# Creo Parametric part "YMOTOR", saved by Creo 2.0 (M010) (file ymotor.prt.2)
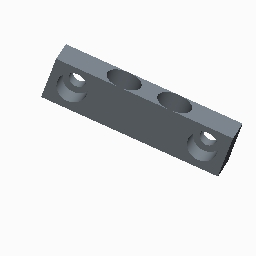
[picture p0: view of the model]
Units: Inch lbm Second (Pro/E Default); INCH, POUND, SECS

Created from: INLBS_PART_SOLID.PRT

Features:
  1. datum plane "RIGHT"
  2. datum plane "TOP"
  3. datum plane "FRONT"
  4. coordinate system
  5. sketch "Sketch 1"
  6. extrusion "Extrude 1", "Sketch 1"
  7. sketch "Sketch 2"
  8. extruded cut "Extrude 2", "Sketch 2"
  9. sketch "Sketch 3"
  10. extruded cut "Extrude 3", "Sketch 3"
  11. sketch "Sketch 4"
  12. extruded cut "Extrude 4", "Sketch 4"
  13. sketch "Sketch 5"
  14. extruded cut "Extrude 5", "Sketch 5"

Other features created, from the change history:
  component interface "INTFC001"
  component interface "INTFC002"

Surfaces: 16 cylinder, 11 plane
